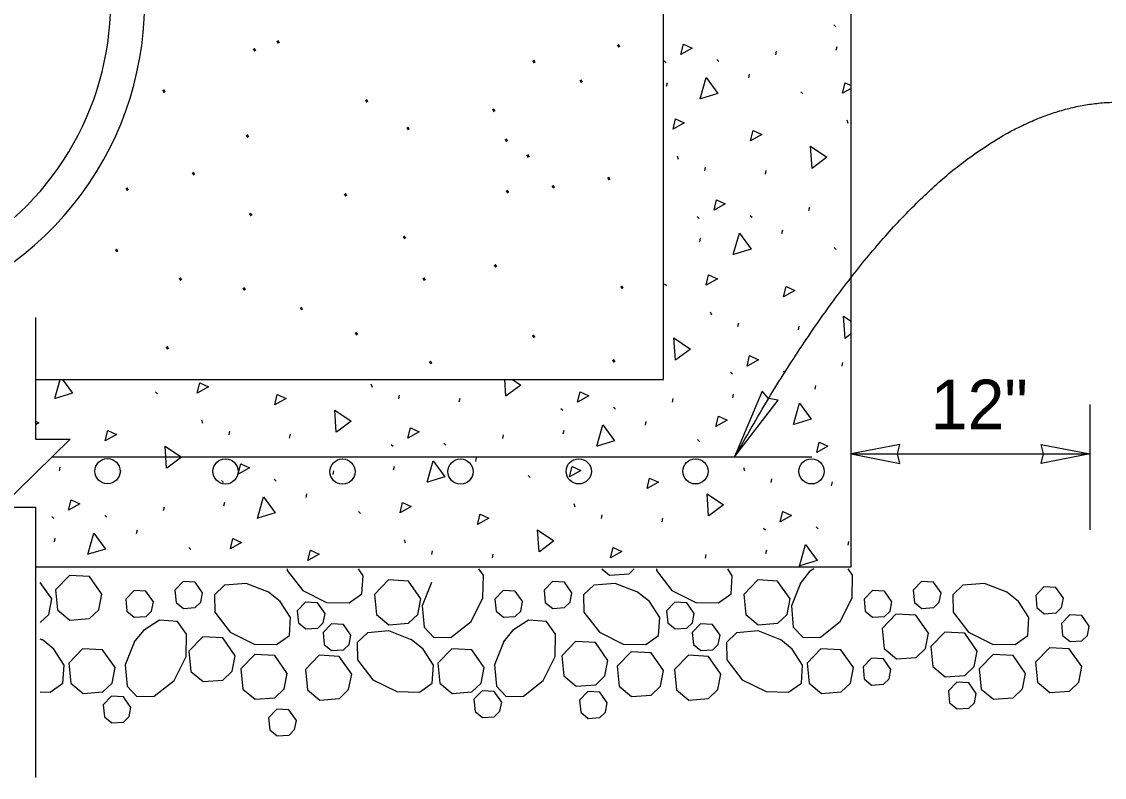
# Model space of a CAD drawing. Extents: x 99862 to 103151, y 100000 to 102076.
# Drawn here: x 101001.8 to 101351.4, y 100515.1 to 100759.3 of the extents above; entities that cross this region are included whole.
import ezdxf

# ---------------------------------------------------------------- set-up
doc = ezdxf.new("R2010")
doc.units = 0
for name, color, linetype in [('Level 1', 7, 'Continuous'), ('Level 15', 7, 'Continuous'), ('Level 16', 7, 'Continuous'), ('Level 17', 7, 'Continuous'), ('Level 18', 7, 'Continuous'), ('Level 20', 7, 'Continuous'), ('Level 23', 7, 'Continuous')]:
    doc.layers.add(name, color=color, linetype=linetype)

msp = doc.modelspace()

# ---------------------------------------------------------------- linework, layer by layer
at = {"layer": 'Level 1'}
msp.add_arc((100936.81, 100765.78), 104.72, 154.3283, 26.0354, dxfattribs=at)
at = {"layer": 'Level 15'}
for p, q in [((101346.73, 100635.64), (101346.73, 100595.14)), ((101269.65, 100619.64), (101346.73, 100619.64))]:
    msp.add_line(p, q, dxfattribs=at)
msp.add_lwpolyline([(101006.25, 100663.69), (101006.25, 100624.41), (101017.45, 100624.41), (100995.05, 100602.42), (101006.25, 100602.42), (101006.25, 100515.14)], dxfattribs=at)
for points in [[(101232.02, 100618.69), (101246.02, 100636.97), (101242.9, 100637.55), (101240.85, 100639.95)], [(101269.65, 100619.64), (101285.37, 100616.56), (101284.65, 100619.64), (101285.37, 100622.72)], [(101346.73, 100619.64), (101331.01, 100616.56), (101331.73, 100619.64), (101331.01, 100622.72)]]:
    msp.add_lwpolyline(points, close=True, dxfattribs=at)
msp.add_open_spline([(101232.02, 100618.69), (101295.84, 100733.33), (101356.07, 100733.33)], degree=2, dxfattribs=at)
at = {"layer": 'Level 16'}
for p, q in [((101264.03, 100758.32), (101264.67, 100757.69)), ((101264.81, 100750.11), (101265.07, 100751.31)), ((101226.29, 100747.06), (101226.93, 100746.43)), ((101245.3, 100748.61), (101245.56, 100749.81)), ((101209.26, 100746.67), (101209.9, 100746.05)), ((101236.59, 100741.18), (101236.84, 100742.38)), ((101210.04, 100738.46), (101210.29, 100739.66)), ((101253.44, 100736.63), (101254.08, 100736.01)), ((101268.22, 100727.58), (101268.57, 100726.51)), ((101213.44, 100715.94), (101213.79, 100714.87)), ((101222.39, 100711.09), (101222.65, 100712.29)), ((101241.94, 100710.04), (101242.19, 100711.24)), ((101256, 100698.29), (101256.26, 100699.49)), ((101219.96, 100696.35), (101220.6, 100695.72)), ((101236.99, 100696.73), (101237.63, 100696.11)), ((101247.29, 100690.86), (101247.54, 100692.05)), ((101220.74, 100688.14), (101220.99, 100689.34)), ((101264.14, 100686.3), (101264.78, 100685.68)), ((101209.36, 100674.66), (101210, 100674.04)), ((101224.14, 100665.61), (101224.49, 100664.54)), ((101233.09, 100660.77), (101233.34, 100661.97)), ((101252.63, 100659.71), (101252.89, 100660.91)), ((101266.7, 100647.96), (101266.95, 100649.16)), ((101230.65, 100646.02), (101231.29, 100645.39)), ((101247.69, 100646.4), (101248.33, 100645.78)), ((101114.58, 100642.33), (101114.94, 100641.26)), ((101045.04, 100639.73), (101045.68, 100639.11)), ((101123.54, 100637.48), (101123.79, 100638.68)), ((101231.43, 100637.81), (101231.69, 100639.01)), ((101257.98, 100640.53), (101258.24, 100641.73)), ((101143.08, 100636.43), (101143.34, 100637.62)), ((101211.92, 100636.32), (101212.18, 100637.51)), ((101175.88, 100634.37), (101176.52, 100633.75)), ((101192.91, 100634.76), (101193.55, 100634.14)), ((101059.81, 100630.68), (101060.16, 100629.61)), ((101203.21, 100628.89), (101203.46, 100630.08)), ((101068.76, 100625.84), (101069.02, 100627.04)), ((101088.31, 100624.78), (101088.56, 100625.98)), ((101157.14, 100624.67), (101157.4, 100625.87)), ((101176.66, 100626.17), (101176.91, 100627.36)), ((101121.1, 100622.73), (101121.74, 100622.11)), ((101138.14, 100623.12), (101138.78, 100622.49)), ((101220.06, 100624.33), (101220.7, 100623.71)), ((101148.43, 100617.24), (101148.68, 100618.44)), ((101013.99, 100614.19), (101014.24, 100615.39)), ((101033.53, 100613.14), (101033.79, 100614.34)), ((101102.37, 100613.03), (101102.62, 100614.23)), ((101121.88, 100614.52), (101122.14, 100615.72)), ((101234.83, 100615.28), (101235.19, 100614.21)), ((101066.32, 100611.09), (101066.96, 100610.46)), ((101083.36, 100611.47), (101084, 100610.85)), ((101165.29, 100612.69), (101165.93, 100612.07)), ((101243.79, 100610.44), (101244.04, 100611.64)), ((101263.33, 100609.38), (101263.59, 100610.58)), ((101067.1, 100602.88), (101067.36, 100604.08)), ((101093.65, 100605.6), (101093.91, 100606.8)), ((101180.06, 100603.64), (101180.41, 100602.57)), ((101047.59, 100601.39), (101047.85, 100602.59)), ((101110.51, 100601.05), (101111.15, 100600.42)), ((101189.01, 100598.8), (101189.27, 100600)), ((101011.55, 100599.45), (101012.19, 100598.82)), ((101028.58, 100599.83), (101029.22, 100599.21)), ((101208.56, 100597.74), (101208.81, 100598.94)), ((101038.88, 100593.96), (101039.13, 100595.15)), ((101241.35, 100595.69), (101241.99, 100595.07)), ((101258.39, 100596.08), (101259.03, 100595.45)), ((101012.33, 100591.24), (101012.58, 100592.44)), ((101125.28, 100592), (101125.64, 100590.93)), ((101268.68, 100590.2), (101268.93, 100591.4)), ((101055.73, 100589.4), (101056.37, 100588.78)), ((101134.24, 100587.15), (101134.49, 100588.35)), ((101153.78, 100586.1), (101154.04, 100587.3)), ((101222.62, 100585.99), (101222.87, 100587.19)), ((101242.13, 100587.48), (101242.39, 100588.68))]:
    msp.add_line(p, q, dxfattribs=at)
for points in [[(101214.65, 100748.71), (101215.47, 100752.06), (101218.29, 100750.75), (101214.65, 100748.71)], [(101220.87, 100734.42), (101222.83, 100741.31), (101226.6, 100736.14), (101220.99, 100734.44)], [(101266.89, 100736.19), (101267.69, 100739.53), (101269.59, 100738.66)], [(101269.59, 100737.71), (101266.89, 100736.19)], [(101212.11, 100724.54), (101212.92, 100727.89), (101215.74, 100726.59), (101212.11, 100724.54)], [(101237.14, 100720.78), (101237.95, 100724.13), (101240.77, 100722.82), (101237.14, 100720.78)], [(101257, 100711.93), (101256.49, 100719.08), (101261.8, 100715.51), (101257.11, 100711.99)], [(101225.35, 100698.38), (101226.16, 100701.73), (101228.98, 100700.42), (101225.35, 100698.38)], [(101231.57, 100684.09), (101233.53, 100690.98), (101237.3, 100685.81), (101231.69, 100684.11)], [(101222.81, 100674.21), (101223.62, 100677.56), (101226.44, 100676.26), (101222.81, 100674.21)], [(101247.84, 100670.45), (101248.65, 100673.8), (101251.47, 100672.49), (101247.84, 100670.45)], [(101267.69, 100656.97), (101267.18, 100664.13), (101269.59, 100662.51)], [(101212.92, 100649.96), (101212.41, 100657.11), (101217.72, 100653.54), (101213.03, 100650.02)], [(101269.48, 100658.31), (101267.69, 100656.97)], [(101236.05, 100648.05), (101236.86, 100651.4), (101239.68, 100650.1), (101236.05, 100648.05)], [(101012.46, 100637.52), (101014.22, 100643.69)], [(101014.95, 100643.69), (101018.2, 100639.24), (101012.58, 100637.54)], [(101058.48, 100639.29), (101059.29, 100642.63), (101062.11, 100641.33), (101058.48, 100639.29)], [(101158.14, 100638.31), (101157.76, 100643.69)], [(101160.27, 100643.69), (101162.94, 100641.89), (101158.25, 100638.38)], [(101083.51, 100635.52), (101084.32, 100638.87), (101087.14, 100637.56), (101083.51, 100635.52)], [(101181.27, 100636.41), (101182.08, 100639.76), (101184.91, 100638.45), (101181.27, 100636.41)], [(101251, 100629.12), (101252.97, 100636.02), (101256.74, 100630.85), (101251.13, 100629.15)], [(101103.37, 100626.67), (101102.86, 100633.82), (101108.17, 100630.25), (101103.47, 100626.73)], [(101225.97, 100628.5), (101226.78, 100631.85), (101229.6, 100630.55), (101225.97, 100628.5)], [(101006.25, 100630.19), (101007.33, 100629.69), (101006.25, 100629.08)], [(101126.5, 100624.77), (101127.31, 100628.12), (101130.13, 100626.81), (101126.5, 100624.77)], [(101187.49, 100622.12), (101189.45, 100629.01), (101193.22, 100623.84), (101187.61, 100622.14)], [(101028.73, 100623.88), (101029.55, 100627.23), (101032.36, 100625.92), (101028.73, 100623.88)], [(101048.59, 100615.03), (101048.08, 100622.18), (101053.39, 100618.61), (101048.7, 100615.09)], [(101258.53, 100620.12), (101259.35, 100623.47), (101262.16, 100622.16), (101258.53, 100620.12)], [(101071.72, 100613.12), (101072.53, 100616.47), (101075.35, 100615.17), (101071.72, 100613.12)], [(101132.71, 100610.47), (101134.68, 100617.37), (101138.45, 100612.2), (101132.83, 100610.5)], [(101178.73, 100612.24), (101179.54, 100615.59), (101182.36, 100614.29), (101178.73, 100612.24)], [(101203.76, 100608.48), (101204.57, 100611.83), (101207.39, 100610.52), (101203.76, 100608.48)], [(101016.94, 100601.48), (101017.76, 100604.83), (101020.58, 100603.52), (101016.94, 100601.48)], [(101077.93, 100598.83), (101079.9, 100605.73), (101083.67, 100600.56), (101078.06, 100598.86)], [(101123.95, 100600.6), (101124.76, 100603.95), (101127.58, 100602.64), (101123.95, 100600.6)], [(101223.62, 100599.63), (101223.11, 100606.78), (101228.42, 100603.21), (101223.72, 100599.69)], [(101148.98, 100596.83), (101149.8, 100600.18), (101152.61, 100598.88), (101148.98, 100596.83)], [(101246.75, 100597.72), (101247.56, 100601.07), (101250.38, 100599.77), (101246.75, 100597.72)], [(101023.16, 100587.19), (101025.12, 100594.08), (101028.89, 100588.91), (101023.28, 100587.21)], [(101168.84, 100587.99), (101168.33, 100595.14), (101173.64, 100591.57), (101168.95, 100588.05)], [(101069.18, 100588.96), (101069.98, 100592.31), (101072.81, 100591), (101069.18, 100588.96)], [(101252.96, 100583.43), (101254.93, 100590.33), (101258.7, 100585.16), (101253.08, 100583.46)], [(101094.21, 100585.19), (101095.02, 100588.54), (101097.84, 100587.24), (101094.21, 100585.19)], [(101191.97, 100586.08), (101192.78, 100589.43), (101195.6, 100588.13), (101191.97, 100586.08)]]:
    msp.add_lwpolyline(points, dxfattribs=at)
at = {"layer": 'Level 17'}
for p, q in [((101269.59, 100583.14), (101269.59, 101611.69)), ((101209.03, 100643.69), (101209.03, 101551.14)), ((101006.25, 100643.69), (101209.03, 100643.69)), ((101006.25, 100583.14), (101269.59, 100583.14))]:
    msp.add_line(p, q, dxfattribs=at)
msp.add_arc((100936.81, 100765.78), 93.72, 178.2436, 3.5092, dxfattribs=at)
at = {"layer": 'Level 18'}
msp.add_line((101011.63, 100618.69), (101256.94, 100618.69), dxfattribs=at)
for centre in [(101029.48, 100614.06), (101067.6, 100614), (101105.38, 100613.94), (101143.48, 100613.94), (101181.67, 100614.01), (101219.38, 100614.02), (101256.83, 100614.01)]:
    msp.add_circle(centre, 4.07, dxfattribs=at)
at = {"layer": 'Level 23'}
for p, q in [((101011.48, 100572.8), (101007.77, 100578.08)), ((101008.66, 100559.46), (101007.77, 100559.81))]:
    msp.add_line(p, q, dxfattribs=at)
for points in [[(101087.5, 100582.53), (101087.52, 100581.95), (101092.52, 100575.56), (101100.24, 100571.69), (101107.53, 100571.56), (101111.63, 100574.48), (101112.01, 100580.28), (101110.57, 100582.53)], [(101134.14, 100578.11), (101131.14, 100570.57), (101131.74, 100563.63), (101134.87, 100560.34), (101140.5, 100560.44), (101146.89, 100565.45), (101150.75, 100573.17), (101150.88, 100580.45), (101149.41, 100582.53)], [(101189.13, 100582.53), (101191.58, 100580.49), (101197.94, 100580.95), (101199.57, 100582.53)], [(101206.73, 100582.53), (101206.74, 100581.95), (101211.74, 100575.56), (101219.47, 100571.69), (101226.75, 100571.56), (101230.85, 100574.48), (101231.24, 100580.28), (101229.79, 100582.53)], [(101253.36, 100578.11), (101250.36, 100570.57), (101250.96, 100563.63), (101254.1, 100560.34), (101259.72, 100560.44), (101266.11, 100565.45), (101269.97, 100573.17), (101270.1, 100580.45), (101268.63, 100582.53)], [(101257.63, 100582.53), (101256.2, 100581.62), (101253.16, 100577.81)], [(101027.7, 100574.31), (101023.66, 100580.04), (101017.22, 100580.41), (101012.74, 100575.77), (101013.39, 100569.27), (101017.37, 100565.96), (101023.73, 100566.42), (101026.72, 100569.32), (101027.69, 100574.31)], [(101044.33, 100571.88), (101041.91, 100575.32), (101038.05, 100575.54), (101035.36, 100572.75), (101035.75, 100568.85), (101038.14, 100566.87), (101041.95, 100567.14), (101043.75, 100568.88), (101044.33, 100571.87)], [(101060.22, 100574.71), (101057.8, 100578.16), (101053.94, 100578.38), (101051.25, 100575.59), (101051.64, 100571.69), (101054.03, 100569.7), (101057.84, 100569.98), (101059.64, 100571.72), (101060.22, 100574.71)], [(101081.77, 100574.83), (101074.23, 100577.82), (101067.3, 100577.22), (101064, 100574.09), (101064.1, 100568.47), (101069.1, 100562.07), (101076.83, 100558.21), (101084.11, 100558.08), (101088.21, 100561), (101088.6, 100566.8), (101085.28, 100571.99), (101081.47, 100575.02)], [(101130.71, 100572.8), (101126.67, 100578.54), (101120.23, 100578.91), (101115.75, 100574.27), (101116.4, 100567.76), (101120.38, 100564.45), (101126.74, 100564.91), (101129.73, 100567.81), (101130.7, 100572.8)], [(101163.56, 100571.88), (101161.13, 100575.32), (101157.27, 100575.54), (101154.58, 100572.75), (101154.97, 100568.85), (101157.36, 100566.87), (101161.17, 100567.14), (101162.97, 100568.88), (101163.55, 100571.87)], [(101179.44, 100574.71), (101177.02, 100578.16), (101173.16, 100578.38), (101170.47, 100575.59), (101170.86, 100571.69), (101173.25, 100569.7), (101177.06, 100569.98), (101178.86, 100571.72), (101179.44, 100574.71)], [(101201, 100574.83), (101193.45, 100577.82), (101186.52, 100577.22), (101183.22, 100574.09), (101183.33, 100568.47), (101188.33, 100562.07), (101196.05, 100558.21), (101203.34, 100558.08), (101207.44, 100561), (101207.82, 100566.8), (101204.5, 100571.99), (101200.69, 100575.02)], [(101249.93, 100572.8), (101245.89, 100578.54), (101239.45, 100578.91), (101234.98, 100574.27), (101235.62, 100567.76), (101239.6, 100564.45), (101245.96, 100564.91), (101248.95, 100567.81), (101249.93, 100572.8)], [(101282.78, 100571.88), (101280.36, 100575.32), (101276.49, 100575.54), (101273.8, 100572.75), (101274.19, 100568.85), (101276.58, 100566.87), (101280.4, 100567.14), (101282.19, 100568.88), (101282.77, 100571.87)], [(101298.67, 100574.71), (101296.24, 100578.16), (101292.38, 100578.38), (101289.7, 100575.59), (101290.08, 100571.69), (101292.47, 100569.7), (101296.29, 100569.98), (101298.08, 100571.72), (101298.66, 100574.71)], [(101320.22, 100574.83), (101312.67, 100577.82), (101305.74, 100577.22), (101302.44, 100574.09), (101302.55, 100568.47), (101307.55, 100562.07), (101315.28, 100558.21), (101322.56, 100558.08), (101326.66, 100561), (101327.05, 100566.8), (101323.72, 100571.99), (101319.91, 100575.02)], [(101338.2, 100573.02), (101335.78, 100576.46), (101331.91, 100576.68), (101329.23, 100573.9), (101329.61, 100569.99), (101332, 100568.01), (101335.82, 100568.28), (101337.61, 100570.02), (101338.19, 100573.02)], [(101007.77, 100565.15), (101010.51, 100567.81), (101011.48, 100572.8)], [(101099.75, 100568.09), (101097.33, 100571.54), (101093.47, 100571.76), (101090.78, 100568.97), (101091.17, 100565.07), (101093.56, 100563.08), (101097.37, 100563.36), (101099.17, 100565.1), (101099.75, 100568.09)], [(101218.97, 100568.09), (101216.55, 100571.54), (101212.69, 100571.76), (101210, 100568.97), (101210.39, 100565.07), (101212.78, 100563.08), (101216.6, 100563.36), (101218.39, 100565.1), (101218.97, 100568.09)], [(101038.24, 100559.08), (101035.24, 100551.53), (101035.84, 100544.6), (101038.98, 100541.3), (101044.6, 100541.41), (101050.99, 100546.41), (101054.85, 100554.14), (101054.98, 100561.42), (101052.07, 100565.52), (101046.27, 100565.91), (101041.08, 100562.58), (101038.04, 100558.77)], [(101157.46, 100559.08), (101154.47, 100551.53), (101155.07, 100544.6), (101158.2, 100541.3), (101163.82, 100541.41), (101170.22, 100546.41), (101174.08, 100554.14), (101174.21, 100561.42), (101171.29, 100565.52), (101165.49, 100565.91), (101160.3, 100562.58), (101157.26, 100558.77)], [(101294.59, 100561.78), (101290.56, 100567.52), (101284.11, 100567.89), (101279.64, 100563.25), (101280.29, 100556.74), (101284.26, 100553.43), (101290.62, 100553.89), (101293.62, 100556.79), (101294.58, 100561.78)], [(101346.52, 100564), (101344.1, 100567.45), (101340.23, 100567.67), (101337.55, 100564.88), (101337.94, 100560.98), (101340.32, 100558.99), (101344.14, 100559.27), (101345.93, 100561.01), (101346.52, 100564)], [(101108.07, 100561.1), (101105.65, 100564.54), (101101.79, 100564.76), (101099.1, 100561.97), (101099.49, 100558.07), (101101.88, 100556.09), (101105.7, 100556.36), (101107.49, 100558.1), (101108.07, 100561.1)], [(101127.89, 100559.46), (101120.34, 100562.45), (101113.41, 100561.85), (101110.11, 100558.72), (101110.22, 100553.09), (101115.22, 100546.7), (101122.95, 100542.84), (101130.23, 100542.71), (101134.33, 100545.62), (101134.72, 100551.43), (101131.39, 100556.61), (101127.58, 100559.65)], [(101227.3, 100561.1), (101224.88, 100564.54), (101221.01, 100564.76), (101218.33, 100561.97), (101218.71, 100558.07), (101221.1, 100556.09), (101224.92, 100556.36), (101226.71, 100558.1), (101227.29, 100561.1)], [(101247.11, 100559.46), (101239.56, 100562.45), (101232.63, 100561.85), (101229.34, 100558.72), (101229.44, 100553.09), (101234.44, 100546.7), (101242.17, 100542.84), (101249.45, 100542.71), (101253.55, 100545.62), (101253.94, 100551.43), (101250.61, 100556.61), (101246.8, 100559.65)], [(101310.33, 100555.96), (101306.3, 100561.7), (101299.86, 100562.07), (101295.38, 100557.42), (101296.03, 100550.92), (101300.01, 100547.61), (101306.37, 100548.07), (101309.36, 100550.97), (101310.33, 100555.96)], [(101007.77, 100542.77), (101011.01, 100542.71), (101015.11, 100545.62), (101015.5, 100551.43), (101012.17, 100556.61), (101008.36, 100559.65)], [(101070.75, 100554.43), (101066.72, 100560.17), (101060.28, 100560.54), (101055.8, 100555.89), (101056.44, 100549.39), (101060.43, 100546.08), (101066.78, 100546.54), (101069.77, 100549.44), (101070.75, 100554.43)], [(101191.11, 100552.93), (101187.08, 100558.67), (101180.64, 100559.04), (101176.16, 100554.39), (101176.81, 100547.89), (101180.79, 100544.58), (101187.14, 100545.04), (101190.14, 100547.94), (101191.11, 100552.93)], [(101031.93, 100550.61), (101027.89, 100556.35), (101021.45, 100556.72), (101016.97, 100552.08), (101017.62, 100545.57), (101021.6, 100542.26), (101027.96, 100542.72), (101030.95, 100545.62), (101031.92, 100550.61)], [(101087.53, 100548.72), (101083.5, 100554.46), (101077.06, 100554.83), (101072.58, 100550.19), (101073.23, 100543.68), (101077.21, 100540.37), (101083.57, 100540.83), (101086.56, 100543.73), (101087.53, 100548.72)], [(101108.34, 100548.49), (101104.31, 100554.22), (101097.87, 100554.59), (101093.39, 100549.95), (101094.04, 100543.44), (101098.02, 100540.13), (101104.38, 100540.6), (101107.37, 100543.5), (101108.34, 100548.48)], [(101151.15, 100550.61), (101147.11, 100556.35), (101140.67, 100556.72), (101136.2, 100552.08), (101136.84, 100545.57), (101140.82, 100542.26), (101147.18, 100542.72), (101150.17, 100545.62), (101151.14, 100550.61)], [(101209.07, 100549.63), (101205.04, 100555.37), (101198.6, 100555.74), (101194.12, 100551.1), (101194.77, 100544.59), (101198.75, 100541.28), (101205.11, 100541.74), (101208.1, 100544.64), (101209.07, 100549.63)], [(101227.57, 100548.49), (101223.53, 100554.22), (101217.09, 100554.59), (101212.61, 100549.95), (101213.26, 100543.44), (101217.24, 100540.13), (101223.6, 100540.6), (101226.59, 100543.5), (101227.56, 100548.48)], [(101270.37, 100550.61), (101266.34, 100556.35), (101259.89, 100556.72), (101255.42, 100552.08), (101256.07, 100545.57), (101260.04, 100542.26), (101266.4, 100542.72), (101269.4, 100545.62), (101270.36, 100550.61)], [(101325.98, 100548.72), (101321.94, 100554.46), (101315.5, 100554.83), (101311.03, 100550.19), (101311.67, 100543.68), (101315.65, 100540.37), (101322.01, 100540.83), (101325, 100543.73), (101325.97, 100548.72)], [(101344.13, 100550.91), (101340.09, 100556.65), (101333.65, 100557.02), (101329.18, 100552.37), (101329.82, 100545.87), (101333.8, 100542.56), (101340.16, 100543.02), (101343.15, 100545.92), (101344.12, 100550.91)], [(101282.46, 100549.99), (101280.03, 100553.44), (101276.17, 100553.66), (101273.49, 100550.87), (101273.87, 100546.97), (101276.26, 100544.98), (101280.08, 100545.26), (101281.87, 100547), (101282.45, 100549.99)], [(101310.01, 100542.25), (101307.59, 100545.7), (101303.73, 100545.92), (101301.04, 100543.13), (101301.43, 100539.23), (101303.82, 100537.24), (101307.63, 100537.52), (101309.43, 100539.26), (101310.01, 100542.25)], [(101037.06, 100537.74), (101034.64, 100541.18), (101030.78, 100541.4), (101028.09, 100538.62), (101028.48, 100534.71), (101030.87, 100532.73), (101034.68, 100533), (101036.48, 100534.75), (101037.06, 100537.74)], [(101156.79, 100539.48), (101154.37, 100542.92), (101150.51, 100543.14), (101147.82, 100540.36), (101148.21, 100536.45), (101150.6, 100534.47), (101154.41, 100534.74), (101156.21, 100536.49), (101156.79, 100539.48)], [(101190.87, 100539.18), (101188.45, 100542.62), (101184.58, 100542.84), (101181.9, 100540.05), (101182.29, 100536.15), (101184.67, 100534.17), (101188.49, 100534.44), (101190.28, 100536.18), (101190.87, 100539.17)], [(101090.49, 100533.54), (101088.06, 100536.99), (101084.2, 100537.21), (101081.51, 100534.42), (101081.9, 100530.52), (101084.29, 100528.53), (101088.11, 100528.81), (101089.9, 100530.55), (101090.48, 100533.54)]]:
    msp.add_lwpolyline(points, dxfattribs=at)

# ---------------------------------------------------------------- texts
at = {"layer": 'Level 1'}
for p in [(101076.2, 100749.22), (101083.83, 100751.76), (101193.78, 100750.49), (101166.45, 100745.4), (101181.7, 100739.05), (101046.97, 100735.87), (101112.43, 100732.69), (101153.48, 100729.67), (101073.94, 100721.34), (101125.78, 100723.8), (101157.55, 100719.98), (101164.54, 100714.9), (101056.5, 100709.19), (101190.64, 100707.61), (101035.11, 100704.18), (101157.9, 100703.39), (101172.68, 100704.97), (101105.62, 100702.33), (101074.99, 100696), (101124.63, 100688.6), (101031.69, 100684.37), (101154.04, 100679.38), (101052.29, 100675.11), (101072.88, 100671.94), (101130.97, 100675.11), (101194.86, 100672.47), (101091.36, 100665.6), (101109.12, 100657.49), (101166.35, 100656.62), (101048.06, 100652.92), (101133.08, 100648.16), (101192.23, 100648.69)]:
    msp.add_text('.', height=6.3, rotation=30.9638, dxfattribs=at).set_placement(p)
at = {"layer": 'Level 20'}
msp.add_text('12"', height=16, dxfattribs=at).set_placement((101295.32, 100627.64))

doc.saveas('drawing.dxf')
